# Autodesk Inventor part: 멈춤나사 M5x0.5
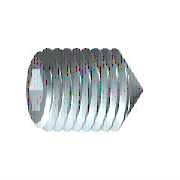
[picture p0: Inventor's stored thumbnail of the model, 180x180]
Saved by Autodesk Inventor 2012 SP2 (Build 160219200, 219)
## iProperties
Company: 한국ATC센터
IsCustomPart: 1
Created: 2014-11
Part Number: 멈춤나사 M5x0.5
Material: 강, 연강
Description: 6각 소켓 머리 없는 멈춤 나사
Document SubType Name: Modeling
Standard: KS B 1028
Designer: KYOUNG IL JANG
Standards Organization: KS
Language: ko-KR
Size Designation: 원추점 M5x10
Categories: <MemberInstance><Categories><Category DisplayName="조임쇠" InternalName="e4da775c-781d-43d5-af7c-5136215cf5a6" Mnemonic="FSTN"><Category DisplayName="볼트" InternalN
Density: 7.86 g/cm^3
Mass: 1.16912 g
Surface Area: 1.91683 cm^2
Volume: 0.148743 cm^3
Author: KYOUNG IL JANG
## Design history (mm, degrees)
revolve "본체" stored, may be unused: angle "d6" = 90 deg
sketch "스케치2"
  geometry: L1 (-0.722, 1.25)-(0.722, 1.25); L2 (0.722, 1.25)-(1.443, 0); L3 (1.443, 0)-(0.722, -1.25); L4 (0.722, -1.25)-(-0.722, -1.25); L5 (-0.722, -1.25)-(-1.443, 0); L6 (-1.443, 0)-(-0.722, 1.25); 3 further points
  constraints: 12 end point, 1 coincident, 1 horizontal, 13 other
extrude "슬롯" join sketch "스케치2" taper "d7" = 0 deg; stored distance "d21" = 10
workaxis "Work Axis1"
workplane "Work Plane1"
body "Solid1"
feature "스레드" dims "d12" = 10 (= NLG), "d13" = 0
chamfer "모따기1" distance "d8" = 2.25 (computed from NND, SPD, FAWI); stored, may be unused: angle "d9" = 45 deg (= FAWI), second distance "d34" = 2.25 (computed from NND, SPD, FAWI)
chamfer "모따기2" distance "d10" = 0.49076 (= -0.5 x GD1 + 0.5 x NND); stored, may be unused: angle "d11" = 45 deg (= FAWI), second distance "d35" = 0.49076 (= -0.5 x GD1 + 0.5 x NND)
sketch "스케치1"
  geometry: L1 (0, 0)-(6.167, 0); L2 (10, 1.443)-(10, 2.5); L3 (10, 2.5)-(0, 2.5); L4 (10, 1.443)-(7, 1.443); L5 (7, 1.443)-(6.167, 0); L6 (0, -0.5)-(0, 3) reference; L7 (0, 2.5)-(0, 0)
  constraints: 13 end point, 3 parallel, 1 collinear, 1 perpendicular, 1 point on line
  dimensions: "d0" = 3 distance of L2.start L4.end (= INTI); "d1" = 60 deg angle of L5 L1; "d2" = 5 diameter of L3 L1 (= NND); "d3" = 2.88675 diameter of L4 L1 (= 1.1547 x SW); "d5" = 10 distance from line of L2 L3.end (= NLG)
other parameters: "NND" = 5 [user parameter; used in 5 equation terms], "NLG" = 10 [user parameter; used in 2 equation terms], "INTI" = 3 [user parameter; used in 1 equation term], "FAWI" = 45 deg [user parameter; used in 4 equation terms], "SW" = 2.5 [user parameter; used in 2 equation terms], "GD1" = 4.01848 (= THREADDIA - 1.2269 x PTC) [user parameter; used in 2 equation terms], "d4" = 0, "FAWI1" = 45 deg [user parameter], "SPD" = 0.5 [user parameter; used in 2 equation terms], "d36" = 0, "d37" = 0, "GUL" = 0.49076 (= 0.61345 x PTC) [user parameter], "TPU" = 12.5 (computed from PTC) [user parameter], "TOA" = 30 deg [user parameter], "THREADDIA" = 5 [user parameter; used in 1 equation term], "PTC" = 0.8 [user parameter; used in 4 equation terms], "GAL" = 0.49076 (= 0.61345 x PTC) [user parameter], "E0" = 2.8875 (= 1.155 x SW) [user parameter]
